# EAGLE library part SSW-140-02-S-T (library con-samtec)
THROUGH-HOLE .025" SQ POST SOCKET Source: Samtec SSW.pdf
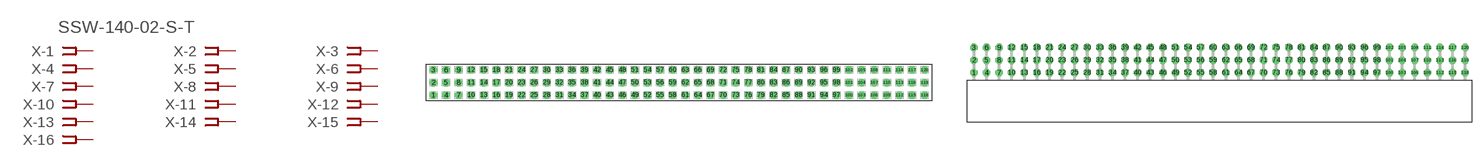
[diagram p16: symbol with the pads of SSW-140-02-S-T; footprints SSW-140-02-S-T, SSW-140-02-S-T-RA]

Designator prefix X; gates -1=FPINV -2=FPIN -3=FPIN -4=FPIN -5=FPIN -6=FPIN -7=FPIN -8=FPIN -9=FPIN -10=FPIN -11=FPIN -12=FPIN -13=FPIN -14=FPIN -15=FPIN -16=FPIN -17=FPIN -18=FPIN -19=FPIN -20=FPIN -21=FPIN -22=FPIN -23=FPIN -24=FPIN -25=FPIN -26=FPIN -27=FPIN -28=FPIN -29=FPIN -30=FPIN -31=FPIN -32=FPIN -33=FPIN -34=FPIN -35=FPIN -36=FPIN -37=FPIN -38=FPIN -39=FPIN -40=FPIN -41=FPIN -42=FPIN -43=FPIN -44=FPIN -45=FPIN -46=FPIN -47=FPIN -48=FPIN -49=FPIN -50=FPIN -51=FPIN -52=FPIN -53=FPIN -54=FPIN -55=FPIN -56=FPIN -57=FPIN -58=FPIN -59=FPIN -60=FPIN -61=FPIN -62=FPIN -63=FPIN -64=FPIN -65=FPIN -66=FPIN -67=FPIN -68=FPIN -69=FPIN -70=FPIN -71=FPIN -72=FPIN -73=FPIN -74=FPIN -75=FPIN -76=FPIN -77=FPIN -78=FPIN -79=FPIN -80=FPIN -81=FPIN -82=FPIN -83=FPIN -84=FPIN -85=FPIN -86=FPIN -87=FPIN -88=FPIN -89=FPIN -90=FPIN -91=FPIN -92=FPIN -93=FPIN -94=FPIN -95=FPIN -96=FPIN -97=FPIN -98=FPIN -99=FPIN -100=FPIN -101=FPIN -102=FPIN -103=FPIN -104=FPIN -105=FPIN -106=FPIN -107=FPIN -108=FPIN -109=FPIN -110=FPIN -111=FPIN -112=FPIN -113=FPIN -114=FPIN -115=FPIN -116=FPIN -117=FPIN -118=FPIN -119=FPIN -120=FPIN

## SSW-140-02-S-T (MPN: SSW-140-02-S-T; OC_FARNELL: unknown; OC_NEWARK: 83P1368)  [SSW-140-02-S-T]
1  -1:1  pas
2  -2:1  pas
3  -3:1  pas
4  -4:1  pas
5  -5:1  pas
6  -6:1  pas
7  -7:1  pas
8  -8:1  pas
9  -9:1  pas
10  -10:1  pas
11  -11:1  pas
12  -12:1  pas
13  -13:1  pas
14  -14:1  pas
15  -15:1  pas
16  -16:1  pas
17  -17:1  pas
18  -18:1  pas
19  -19:1  pas
20  -20:1  pas
21  -21:1  pas
22  -22:1  pas
23  -23:1  pas
24  -24:1  pas
25  -25:1  pas
26  -26:1  pas
27  -27:1  pas
28  -28:1  pas
29  -29:1  pas
30  -30:1  pas
31  -31:1  pas
32  -32:1  pas
33  -33:1  pas
34  -34:1  pas
35  -35:1  pas
36  -36:1  pas
37  -37:1  pas
38  -38:1  pas
39  -39:1  pas
40  -40:1  pas
41  -41:1  pas
42  -42:1  pas
43  -43:1  pas
44  -44:1  pas
45  -45:1  pas
46  -46:1  pas
47  -47:1  pas
48  -48:1  pas
49  -49:1  pas
50  -50:1  pas
51  -51:1  pas
52  -52:1  pas
53  -53:1  pas
54  -54:1  pas
55  -55:1  pas
56  -56:1  pas
57  -57:1  pas
58  -58:1  pas
59  -59:1  pas
60  -60:1  pas
61  -61:1  pas
62  -62:1  pas
63  -63:1  pas
64  -64:1  pas
65  -65:1  pas
66  -66:1  pas
67  -67:1  pas
68  -68:1  pas
69  -69:1  pas
70  -70:1  pas
71  -71:1  pas
72  -72:1  pas
73  -73:1  pas
74  -74:1  pas
75  -75:1  pas
76  -76:1  pas
77  -77:1  pas
78  -78:1  pas
79  -79:1  pas
80  -80:1  pas
81  -81:1  pas
82  -82:1  pas
83  -83:1  pas
84  -84:1  pas
85  -85:1  pas
86  -86:1  pas
87  -87:1  pas
88  -88:1  pas
89  -89:1  pas
90  -90:1  pas
91  -91:1  pas
92  -92:1  pas
93  -93:1  pas
94  -94:1  pas
95  -95:1  pas
96  -96:1  pas
97  -97:1  pas
98  -98:1  pas
99  -99:1  pas
100  -100:1  pas
101  -101:1  pas
102  -102:1  pas
103  -103:1  pas
104  -104:1  pas
105  -105:1  pas
106  -106:1  pas
107  -107:1  pas
108  -108:1  pas
109  -109:1  pas
110  -110:1  pas
111  -111:1  pas
112  -112:1  pas
113  -113:1  pas
114  -114:1  pas
115  -115:1  pas
116  -116:1  pas
117  -117:1  pas
118  -118:1  pas
119  -119:1  pas
120  -120:1  pas

## SSW-140-02-S-TRA (MPN: SSW-140-02-S-T-RA; OC_FARNELL: unknown; OC_NEWARK: 83P1369)  [SSW-140-02-S-T-RA]
Pads as for SSW-140-02-S-T

## Footprint SSW-140-02-S-T (pad centres in mm)
THROUGH-HOLE .025" SQ POST SOCKET Source: Samtec SSW.pdf
drill 1 pad 1.5 octagon: 1 -49.53,-2.54; 2 -49.53,0; 3 -49.53,2.54; 4 -46.99,-2.54; 5 -46.99,0; 6 -46.99,2.54; 7 -44.45,-2.54; 8 -44.45,0; 9 -44.45,2.54; 10 -41.91,-2.54; 11 -41.91,0; 12 -41.91,2.54; 13 -39.37,-2.54; 14 -39.37,0; 15 -39.37,2.54; 16 -36.83,-2.54; 17 -36.83,0; 18 -36.83,2.54; 19 -34.29,-2.54; 20 -34.29,0; 21 -34.29,2.54; 22 -31.75,-2.54; 23 -31.75,0; 24 -31.75,2.54; 25 -29.21,-2.54; 26 -29.21,0; 27 -29.21,2.54; 28 -26.67,-2.54; 29 -26.67,0; 30 -26.67,2.54; 31 -24.13,-2.54; 32 -24.13,0; 33 -24.13,2.54; 34 -21.59,-2.54; 35 -21.59,0; 36 -21.59,2.54; 37 -19.05,-2.54; 38 -19.05,0; 39 -19.05,2.54; 40 -16.51,-2.54; 41 -16.51,0; 42 -16.51,2.54; 43 -13.97,-2.54; 44 -13.97,0; 45 -13.97,2.54; 46 -11.43,-2.54; 47 -11.43,0; 48 -11.43,2.54; 49 -8.89,-2.54; 50 -8.89,0; 51 -8.89,2.54; 52 -6.35,-2.54; 53 -6.35,0; 54 -6.35,2.54; 55 -3.81,-2.54; 56 -3.81,0; 57 -3.81,2.54; 58 -1.27,-2.54; 59 -1.27,0; 60 -1.27,2.54; 61 1.27,-2.54; 62 1.27,0; 63 1.27,2.54; 64 3.81,-2.54; 65 3.81,0; 66 3.81,2.54; 67 6.35,-2.54; 68 6.35,0; 69 6.35,2.54; 70 8.89,-2.54; 71 8.89,0; 72 8.89,2.54; 73 11.43,-2.54; 74 11.43,0; 75 11.43,2.54; 76 13.97,-2.54; 77 13.97,0; 78 13.97,2.54; 79 16.51,-2.54; 80 16.51,0; 81 16.51,2.54; 82 19.05,-2.54; 83 19.05,0; 84 19.05,2.54; 85 21.59,-2.54; 86 21.59,0; 87 21.59,2.54; 88 24.13,-2.54; 89 24.13,0; 90 24.13,2.54; 91 26.67,-2.54; 92 26.67,0; 93 26.67,2.54; 94 29.21,-2.54; 95 29.21,0; 96 29.21,2.54; 97 31.75,-2.54; 98 31.75,0; 99 31.75,2.54; 100 34.29,-2.54; 101 34.29,0; 102 34.29,2.54; 103 36.83,-2.54; 104 36.83,0; 105 36.83,2.54; 106 39.37,-2.54; 107 39.37,0; 108 39.37,2.54; 109 41.91,-2.54; 110 41.91,0; 111 41.91,2.54; 112 44.45,-2.54; 113 44.45,0; 114 44.45,2.54; 115 46.99,-2.54; 116 46.99,0; 117 46.99,2.54; 118 49.53,-2.54; 119 49.53,0; 120 49.53,2.54

## Footprint SSW-140-02-S-T-RA (pad centres in mm)
THROUGH-HOLE .025" SQ POST SOCKET Source: Samtec SSW.pdf
drill 1 pad 1.5 octagon: 1 -49.53,1.524; 2 -49.53,4.064; 3 -49.53,6.604; 4 -46.99,1.524; 5 -46.99,4.064; 6 -46.99,6.604; 7 -44.45,1.524; 8 -44.45,4.064; 9 -44.45,6.604; 10 -41.91,1.524; 11 -41.91,4.064; 12 -41.91,6.604; 13 -39.37,1.524; 14 -39.37,4.064; 15 -39.37,6.604; 16 -36.83,1.524; 17 -36.83,4.064; 18 -36.83,6.604; 19 -34.29,1.524; 20 -34.29,4.064; 21 -34.29,6.604; 22 -31.75,1.524; 23 -31.75,4.064; 24 -31.75,6.604; 25 -29.21,1.524; 26 -29.21,4.064; 27 -29.21,6.604; 28 -26.67,1.524; 29 -26.67,4.064; 30 -26.67,6.604; 31 -24.13,1.524; 32 -24.13,4.064; 33 -24.13,6.604; 34 -21.59,1.524; 35 -21.59,4.064; 36 -21.59,6.604; 37 -19.05,1.524; 38 -19.05,4.064; 39 -19.05,6.604; 40 -16.51,1.524; 41 -16.51,4.064; 42 -16.51,6.604; 43 -13.97,1.524; 44 -13.97,4.064; 45 -13.97,6.604; 46 -11.43,1.524; 47 -11.43,4.064; 48 -11.43,6.604; 49 -8.89,1.524; 50 -8.89,4.064; 51 -8.89,6.604; 52 -6.35,1.524; 53 -6.35,4.064; 54 -6.35,6.604; 55 -3.81,1.524; 56 -3.81,4.064; 57 -3.81,6.604; 58 -1.27,1.524; 59 -1.27,4.064; 60 -1.27,6.604; 61 1.27,1.524; 62 1.27,4.064; 63 1.27,6.604; 64 3.81,1.524; 65 3.81,4.064; 66 3.81,6.604; 67 6.35,1.524; 68 6.35,4.064; 69 6.35,6.604; 70 8.89,1.524; 71 8.89,4.064; 72 8.89,6.604; 73 11.43,1.524; 74 11.43,4.064; 75 11.43,6.604; 76 13.97,1.524; 77 13.97,4.064; 78 13.97,6.604; 79 16.51,1.524; 80 16.51,4.064; 81 16.51,6.604; 82 19.05,1.524; 83 19.05,4.064; 84 19.05,6.604; 85 21.59,1.524; 86 21.59,4.064; 87 21.59,6.604; 88 24.13,1.524; 89 24.13,4.064; 90 24.13,6.604; 91 26.67,1.524; 92 26.67,4.064; 93 26.67,6.604; 94 29.21,1.524; 95 29.21,4.064; 96 29.21,6.604; 97 31.75,1.524; 98 31.75,4.064; 99 31.75,6.604; 100 34.29,1.524; 101 34.29,4.064; 102 34.29,6.604; 103 36.83,1.524; 104 36.83,4.064; 105 36.83,6.604; 106 39.37,1.524; 107 39.37,4.064; 108 39.37,6.604; 109 41.91,1.524; 110 41.91,4.064; 111 41.91,6.604; 112 44.45,1.524; 113 44.45,4.064; 114 44.45,6.604; 115 46.99,1.524; 116 46.99,4.064; 117 46.99,6.604; 118 49.53,1.524; 119 49.53,4.064; 120 49.53,6.604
